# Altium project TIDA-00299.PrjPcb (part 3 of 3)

## Sheet AMIC110 ICE EVM_SC_0.SchDoc
size 431 x 279 mm; Date: Not shown in title block; ApprovedBy: Not shown in title block; CheckedBy: Not shown in title block; Author: Not shown in title block; CompanyName: Not shown in title block; Engineer: Not shown in title block; Organization: Not shown in title block; Address1: Not shown in title block; Address2: Not shown in title block; Address3: Not shown in title block; Address4: Not shown in title block; DocumentNumber: 1; Revision: Use project parameter SCH_Rev; SheetNumber: 5; SheetTotal: 1; PageSetup: Record=PageOptions¦CenterHorizontal=True¦CenterVertical=True¦PrintScale=1.00¦XCorrection=1.00¦YCorrection=1.00¦PrintKind=0¦BorderSize=5000000¦LeftOffset=0¦BottomOffset=0¦Orientation=2¦PaperLength=1000¦PaperWidth=1000¦Scale=100¦PaperSource=15¦PrintQuality=600¦MediaType=1¦DitherType=10¦PaperKind=Letter¦PrintScaleMode=1
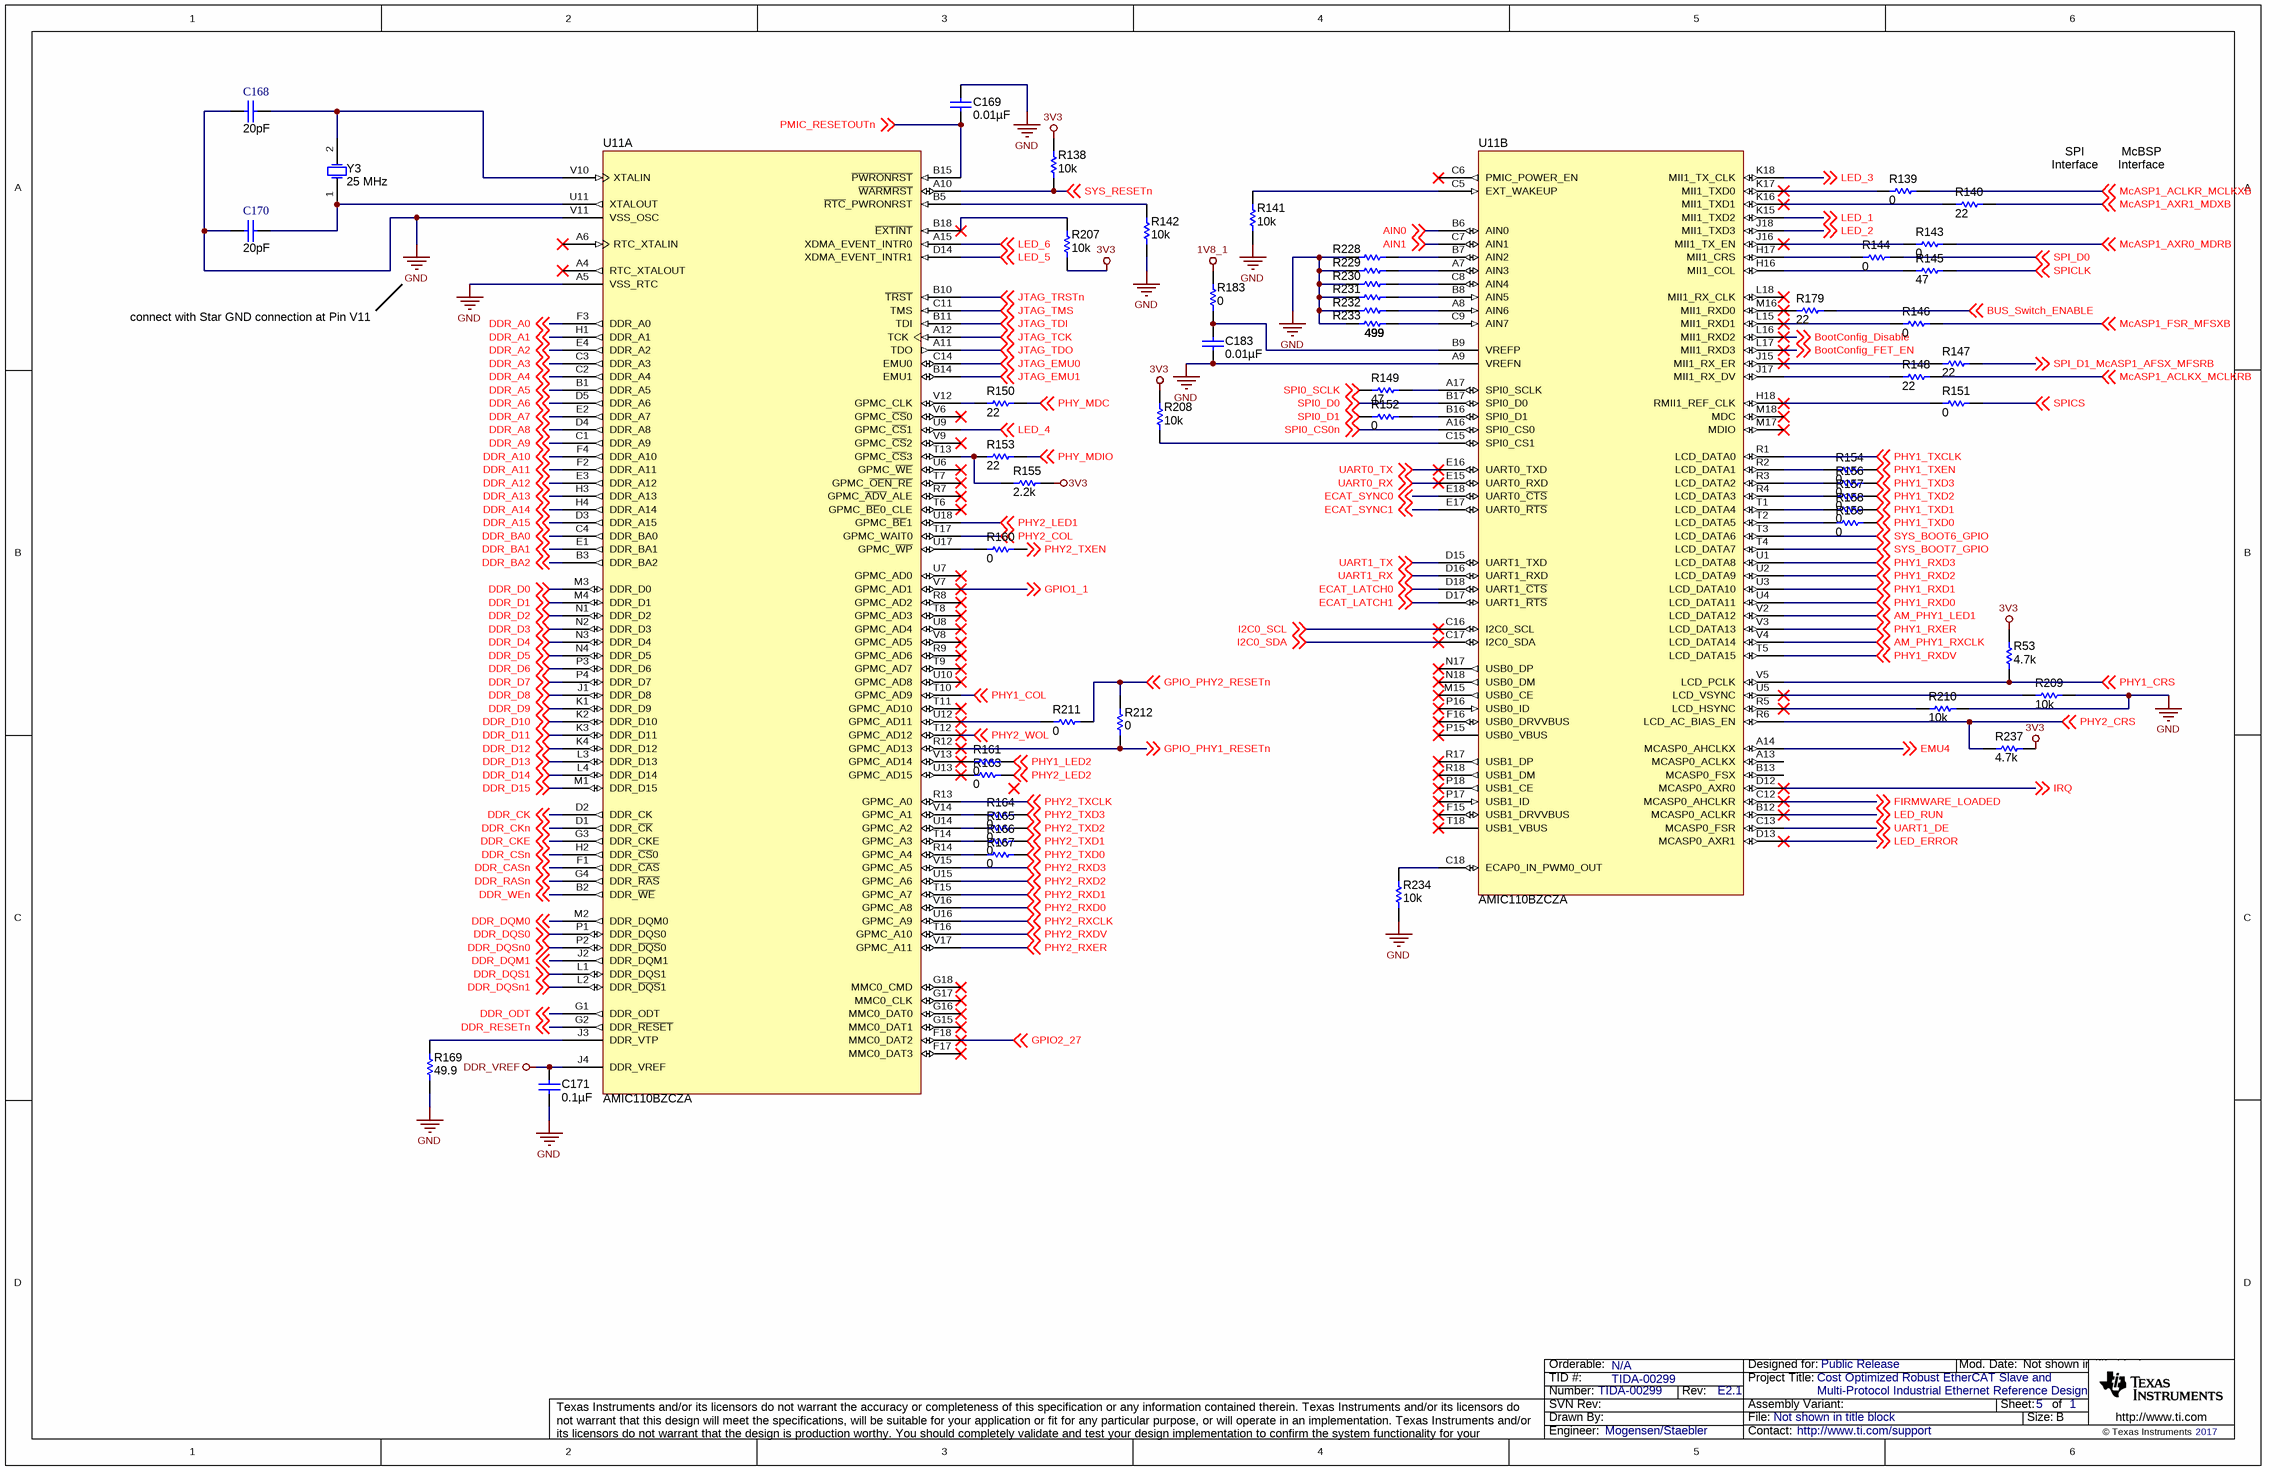
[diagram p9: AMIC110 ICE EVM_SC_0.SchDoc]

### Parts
C168  ValueDisplayed: 20pF  [0402]  (hidden comment: GRM1555C1H200JA01D)
C169  ValueDisplayed: 0.01µF  [0201L]  (hidden comment: GRM033R71A103KA01D)
C170  ValueDisplayed: 20pF  [0402]  (hidden comment: GRM1555C1H200JA01D)
C171  ValueDisplayed: 0.1µF  [0402]  (hidden comment: GRM155R70J104KA01D)
C183  ValueDisplayed: 0.01µF  [0201L]  (hidden comment: GRM033R71A103KA01D)
R53  ValueDisplayed: 4.7k  [0402L]  (hidden comment: CRCW04024K70JNED)
R138  ValueDisplayed: 10k  [0402L]  (hidden comment: CRCW040210K0JNED)
R139  ValueDisplayed: 0  [0402L]  (hidden comment: CRCW04020000Z0ED)
R140  ValueDisplayed: 22  [0402L]  (hidden comment: CRCW040222R0JNED)
R141  ValueDisplayed: 10k  [0402L]  (hidden comment: CRCW040210K0JNED)
R142  ValueDisplayed: 10k  [0402L]  (hidden comment: CRCW040210K0JNED)
R143  ValueDisplayed: 0  [0402L]  (hidden comment: CRCW04020000Z0ED)
R144  ValueDisplayed: 0  [0402L]  (hidden comment: CRCW04020000Z0ED)
R145  ValueDisplayed: 47  [0402L]  (hidden comment: CRCW040247R0JNED)
R146  ValueDisplayed: 0  [0402L]  (hidden comment: CRCW04020000Z0ED)
R147  ValueDisplayed: 22  [0402L]  (hidden comment: CRCW040222R0JNED)
R148  ValueDisplayed: 22  [0402L]  (hidden comment: CRCW040222R0JNED)
R149  ValueDisplayed: 47  [0402L]  (hidden comment: CRCW040247R0JNED)
R150  ValueDisplayed: 22  [0402L]  (hidden comment: CRCW040222R0JNED)
R151  ValueDisplayed: 0  [0402L]  (hidden comment: CRCW04020000Z0ED)
R152  ValueDisplayed: 0  [0402L]  (hidden comment: CRCW04020000Z0ED)
R153  ValueDisplayed: 22  [0402L]  (hidden comment: CRCW040222R0JNED)
R154  ValueDisplayed: 0  [0402L]  (hidden comment: CRCW04020000Z0ED)
R155  ValueDisplayed: 2.2k  [0402L]  (hidden comment: CRCW04022K20JNED)
R156  ValueDisplayed: 0  [0402L]  (hidden comment: CRCW04020000Z0ED)
R157  ValueDisplayed: 0  [0402L]  (hidden comment: CRCW04020000Z0ED)
R158  ValueDisplayed: 0  [0402L]  (hidden comment: CRCW04020000Z0ED)
R159  ValueDisplayed: 0  [0402L]  (hidden comment: CRCW04020000Z0ED)
R160  ValueDisplayed: 0  [0402L]  (hidden comment: CRCW04020000Z0ED)
R161  ValueDisplayed: 0  [0402L]  (hidden comment: CRCW04020000Z0ED)
R163  ValueDisplayed: 0  [0402L]  (hidden comment: CRCW04020000Z0ED)
R164  ValueDisplayed: 0  [0402L]  (hidden comment: CRCW04020000Z0ED)
R165  ValueDisplayed: 0  [0402L]  (hidden comment: CRCW04020000Z0ED)
R166  ValueDisplayed: 0  [0402L]  (hidden comment: CRCW04020000Z0ED)
R167  ValueDisplayed: 0  [0402L]  (hidden comment: CRCW04020000Z0ED)
R169  ValueDisplayed: 49.9  [0402]  (hidden comment: CRCW040249R9FKED)
R179  ValueDisplayed: 22  [0402L]  (hidden comment: CRCW040222R0JNED)
R183  ValueDisplayed: 0  [0402L]  (hidden comment: CRCW04020000Z0ED)
R207  ValueDisplayed: 10k  [0402L]  (hidden comment: CRCW040210K0JNED)
R208  ValueDisplayed: 10k  [0402L]  (hidden comment: CRCW040210K0JNED)
R209  ValueDisplayed: 10k  [0402L]  (hidden comment: CRCW040210K0JNED)
R210  ValueDisplayed: 10k  [0402L]  (hidden comment: CRCW040210K0JNED)
R211  ValueDisplayed: 0  [0402L]  (hidden comment: CRCW04020000Z0ED)
R212  ValueDisplayed: 0  [0402L]  (hidden comment: CRCW04020000Z0ED)
R228  ValueDisplayed: 499  [0201L]  (hidden comment: CRCW0201499RFKED)
R229  ValueDisplayed: 499  [0201L]  (hidden comment: CRCW0201499RFKED)
R230  ValueDisplayed: 499  [0201L]  (hidden comment: CRCW0201499RFKED)
R231  ValueDisplayed: 499  [0201L]  (hidden comment: CRCW0201499RFKED)
R232  ValueDisplayed: 499  [0201L]  (hidden comment: CRCW0201499RFKED)
R233  ValueDisplayed: 499  [0201L]  (hidden comment: CRCW0201499RFKED)
R234  ValueDisplayed: 10k  [0402L]  (hidden comment: CRCW040210K0JNED)
R237  ValueDisplayed: 4.7k  [0402L]  (hidden comment: CRCW04024K70JNED)
U11  AMIC110BZCZA  [ZCZ0324A]  (parts A,B of 4)
Y3  Frequency: 25 MHz  [XTAL_ABM3]  (hidden comment: CTX1175TR-ND)

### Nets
1V8_1: R183.2
3V3: R53.2 R138.2 R155.2 R207.1 R208.1 R237.1
DDR_VREF: C171.1 U11.J4(DDR_VREF)
GND: C168.2 C169.1 C170.2 C171.2 C183.2 R141.1 R142.1 R169.1 R209.2 R210.2 R228.1 R229.1 R230.1 R231.1 R232.1 R233.1 R234.1 U11.A5(VSS_RTC) U11.A9(VREFN) U11.V11(VSS_OSC)
AIN0: U11.B6(AIN0) ; off-sheet AIN0
AIN1: U11.C7(AIN1) ; off-sheet AIN1
AM_PHY1_LED1: U11.V2(LCD_DATA12) ; off-sheet AM_PHY1_LED1
AM_PHY1_RXCLK: U11.V4(LCD_DATA14) ; off-sheet AM_PHY1_RXCLK
BootConfig_Disable: U11.L16(MII1_RXD2) ; off-sheet BootConfig_Disable
BootConfig_FET_EN: U11.L17(MII1_RXD3) ; off-sheet BootConfig_FET_EN
BUS_Switch_ENABLE: R179.2 ; off-sheet BUS_Switch_ENABLE
DDR_A0: U11.F3(DDR_A0) ; off-sheet DDR_A0
DDR_A1: U11.H1(DDR_A1) ; off-sheet DDR_A1
DDR_A2: U11.E4(DDR_A2) ; off-sheet DDR_A2
DDR_A3: U11.C3(DDR_A3) ; off-sheet DDR_A3
DDR_A4: U11.C2(DDR_A4) ; off-sheet DDR_A4
DDR_A5: U11.B1(DDR_A5) ; off-sheet DDR_A5
DDR_A6: U11.D5(DDR_A6) ; off-sheet DDR_A6
DDR_A7: U11.E2(DDR_A7) ; off-sheet DDR_A7
DDR_A8: U11.D4(DDR_A8) ; off-sheet DDR_A8
DDR_A9: U11.C1(DDR_A9) ; off-sheet DDR_A9
DDR_A10: U11.F4(DDR_A10) ; off-sheet DDR_A10
DDR_A11: U11.F2(DDR_A11) ; off-sheet DDR_A11
DDR_A12: U11.E3(DDR_A12) ; off-sheet DDR_A12
DDR_A13: U11.H3(DDR_A13) ; off-sheet DDR_A13
DDR_A14: U11.H4(DDR_A14) ; off-sheet DDR_A14
DDR_A15: U11.D3(DDR_A15) ; off-sheet DDR_A15
DDR_BA0: U11.C4(DDR_BA0) ; off-sheet DDR_BA0
DDR_BA1: U11.E1(DDR_BA1) ; off-sheet DDR_BA1
DDR_BA2: U11.B3(DDR_BA2) ; off-sheet DDR_BA2
DDR_CASn: U11.F1(DDR_~{CAS}) ; off-sheet DDR_CASn
DDR_CK: U11.D2(DDR_CK) ; off-sheet DDR_CK
DDR_CKE: U11.G3(DDR_CKE) ; off-sheet DDR_CKE
DDR_CKn: U11.D1(DDR_~{CK}) ; off-sheet DDR_CKn
DDR_CSn: U11.H2(DDR_~{CS}0) ; off-sheet DDR_CSn
DDR_D0: U11.M3(DDR_D0) ; off-sheet DDR_D0
DDR_D1: U11.M4(DDR_D1) ; off-sheet DDR_D1
DDR_D2: U11.N1(DDR_D2) ; off-sheet DDR_D2
DDR_D3: U11.N2(DDR_D3) ; off-sheet DDR_D3
DDR_D4: U11.N3(DDR_D4) ; off-sheet DDR_D4
DDR_D5: U11.N4(DDR_D5) ; off-sheet DDR_D5
DDR_D6: U11.P3(DDR_D6) ; off-sheet DDR_D6
DDR_D7: U11.P4(DDR_D7) ; off-sheet DDR_D7
DDR_D8: U11.J1(DDR_D8) ; off-sheet DDR_D8
DDR_D9: U11.K1(DDR_D9) ; off-sheet DDR_D9
DDR_D10: U11.K2(DDR_D10) ; off-sheet DDR_D10
DDR_D11: U11.K3(DDR_D11) ; off-sheet DDR_D11
DDR_D12: U11.K4(DDR_D12) ; off-sheet DDR_D12
DDR_D13: U11.L3(DDR_D13) ; off-sheet DDR_D13
DDR_D14: U11.L4(DDR_D14) ; off-sheet DDR_D14
DDR_D15: U11.M1(DDR_D15) ; off-sheet DDR_D15
DDR_DQM0: U11.M2(DDR_DQM0) ; off-sheet DDR_DQM0
DDR_DQM1: U11.J2(DDR_DQM1) ; off-sheet DDR_DQM1
DDR_DQS0: U11.P1(DDR_DQS0) ; off-sheet DDR_DQS0
DDR_DQS1: U11.L1(DDR_DQS1) ; off-sheet DDR_DQS1
DDR_DQSn0: U11.P2(DDR_~{DQS}0) ; off-sheet DDR_DQSn0
DDR_DQSn1: U11.L2(DDR_~{DQS}1) ; off-sheet DDR_DQSn1
DDR_ODT: U11.G1(DDR_ODT) ; off-sheet DDR_ODT
DDR_RASn: U11.G4(DDR_~{RAS}) ; off-sheet DDR_RASn
DDR_RESETn: U11.G2(DDR_~{RESET}) ; off-sheet DDR_RESETn
DDR_WEn: U11.B2(DDR_~{WE}) ; off-sheet DDR_WEn
ECAT_LATCH0: U11.D18(UART1_~{CTS}) ; off-sheet ECAT_LATCH0
ECAT_LATCH1: U11.D17(UART1_~{RTS}) ; off-sheet ECAT_LATCH1
ECAT_SYNC0: U11.E18(UART0_~{CTS}) ; off-sheet ECAT_SYNC0
ECAT_SYNC1: U11.E17(UART0_~{RTS}) ; off-sheet ECAT_SYNC1
EMU4: U11.A14(MCASP0_AHCLKX) ; off-sheet EMU4
FIRMWARE_LOADED: U11.C12(MCASP0_AHCLKR) ; off-sheet FIRMWARE_LOADED
GPIO1_1: U11.V7(GPMC_AD1) ; off-sheet GPIO1_1
GPIO2_27: U11.F18(MMC0_DAT2) ; off-sheet GPIO2_27
GPIO_PHY1_RESETn: R212.2 U11.R12(GPMC_AD13) ; off-sheet GPIO_PHY1_RESETn
GPIO_PHY2_RESETn: R211.1 R212.1 ; off-sheet GPIO_PHY2_RESETn
I2C0_SCL: U11.C16(I2C0_SCL) ; off-sheet I2C0_SCL
I2C0_SDA: U11.C17(I2C0_SDA) ; off-sheet I2C0_SDA
IRQ: U11.D12(MCASP0_AXR0) ; off-sheet IRQ
JTAG_EMU0: U11.C14(EMU0) ; off-sheet JTAG_EMU0
JTAG_EMU1: U11.B14(EMU1) ; off-sheet JTAG_EMU1
JTAG_TCK: U11.A12(TCK) ; off-sheet JTAG_TCK
JTAG_TDI: U11.B11(TDI) ; off-sheet JTAG_TDI
JTAG_TDO: U11.A11(TDO) ; off-sheet JTAG_TDO
JTAG_TMS: U11.C11(TMS) ; off-sheet JTAG_TMS
JTAG_TRSTn: U11.B10(~{TRST}) ; off-sheet JTAG_TRSTn
LED_1: U11.K15(MII1_TXD2) ; off-sheet LED_1
LED_2: U11.J18(MII1_TXD3) ; off-sheet LED_2
LED_3: U11.K18(MII1_TX_CLK) ; off-sheet LED_3
LED_4: U11.U9(GPMC_~{CS}1) ; off-sheet LED_4
LED_5: U11.D14(XDMA_EVENT_INTR1) ; off-sheet LED_5
LED_6: U11.A15(XDMA_EVENT_INTR0) ; off-sheet LED_6
LED_ERROR: U11.D13(MCASP0_AXR1) ; off-sheet LED_ERROR
LED_RUN: U11.B12(MCASP0_ACLKR) ; off-sheet LED_RUN
McASP1_ACLKR_MCLKXB: R139.2 ; off-sheet McASP1_ACLKR_MCLKXB
McASP1_ACLKX_MCLKRB: R148.2 ; off-sheet McASP1_ACLKX_MCLKRB
McASP1_AXR0_MDRB: R143.2 ; off-sheet McASP1_AXR0_MDRB
McASP1_AXR1_MDXB: R140.2 ; off-sheet McASP1_AXR1_MDXB
McASP1_FSR_MFSXB: R146.2 ; off-sheet McASP1_FSR_MFSXB
PHY1_COL: U11.T10(GPMC_AD9) ; off-sheet PHY1_COL
PHY1_CRS: R53.1 U11.V5(LCD_PCLK) ; off-sheet PHY1_CRS
PHY1_LED2: R161.1 ; off-sheet PHY1_LED2
PHY1_RXD0: U11.U4(LCD_DATA11) ; off-sheet PHY1_RXD0
PHY1_RXD1: U11.U3(LCD_DATA10) ; off-sheet PHY1_RXD1
PHY1_RXD2: U11.U2(LCD_DATA9) ; off-sheet PHY1_RXD2
PHY1_RXD3: U11.U1(LCD_DATA8) ; off-sheet PHY1_RXD3
PHY1_RXDV: U11.T5(LCD_DATA15) ; off-sheet PHY1_RXDV
PHY1_RXER: U11.V3(LCD_DATA13) ; off-sheet PHY1_RXER
PHY1_TXCLK: U11.R1(LCD_DATA0) ; off-sheet PHY1_TXCLK
PHY1_TXD0: R159.2 ; off-sheet PHY1_TXD0
PHY1_TXD1: R158.2 ; off-sheet PHY1_TXD1
PHY1_TXD2: R157.2 ; off-sheet PHY1_TXD2
PHY1_TXD3: R156.2 ; off-sheet PHY1_TXD3
PHY1_TXEN: R154.2 ; off-sheet PHY1_TXEN
PHY2_COL: U11.T17(GPMC_WAIT0) ; off-sheet PHY2_COL
PHY2_CRS: R237.2 U11.R6(LCD_AC_BIAS_EN) ; off-sheet PHY2_CRS
PHY2_LED1: U11.U18(GPMC_~{BE}1) ; off-sheet PHY2_LED1
PHY2_LED2: R163.1 ; off-sheet PHY2_LED2
PHY2_RXCLK: U11.U16(GPMC_A9) ; off-sheet PHY2_RXCLK
PHY2_RXD0: U11.V16(GPMC_A8) ; off-sheet PHY2_RXD0
PHY2_RXD1: U11.T15(GPMC_A7) ; off-sheet PHY2_RXD1
PHY2_RXD2: U11.U15(GPMC_A6) ; off-sheet PHY2_RXD2
PHY2_RXD3: U11.V15(GPMC_A5) ; off-sheet PHY2_RXD3
PHY2_RXDV: U11.T16(GPMC_A10) ; off-sheet PHY2_RXDV
PHY2_RXER: U11.V17(GPMC_A11) ; off-sheet PHY2_RXER
PHY2_TXCLK: U11.R13(GPMC_A0) ; off-sheet PHY2_TXCLK
PHY2_TXD0: R167.2 ; off-sheet PHY2_TXD0
PHY2_TXD1: R166.2 ; off-sheet PHY2_TXD1
PHY2_TXD2: R165.2 ; off-sheet PHY2_TXD2
PHY2_TXD3: R164.2 ; off-sheet PHY2_TXD3
PHY2_TXEN: R160.2 ; off-sheet PHY2_TXEN
PHY2_WOL: U11.T12(GPMC_AD12) ; off-sheet PHY2_WOL
PHY_MDC: R150.1 ; off-sheet PHY_MDC
PHY_MDIO: R153.1 ; off-sheet PHY_MDIO
PMIC_RESETOUTn: C169.2 U11.B15(~{PWRONRST}) ; off-sheet PMIC_RESETOUTn
SPI0_CS0n: U11.A16(SPI0_CS0) ; off-sheet SPI0_CS0n
SPI0_D0: U11.B17(SPI0_D0) ; off-sheet SPI0_D0
SPI0_D1: R152.1 ; off-sheet SPI0_D1
SPI0_SCLK: R149.1 ; off-sheet SPI0_SCLK
SPI_D0: R144.2 ; off-sheet SPI_D0
SPI_D1_McASP1_AFSX_MFSRB: R147.2 ; off-sheet SPI_D1_McASP1_AFSX_MFSRB
SPICLK: R145.2 ; off-sheet SPICLK
SPICS: R151.2 ; off-sheet SPICS
SYS_BOOT6_GPIO: U11.T3(LCD_DATA6) ; off-sheet SYS_BOOT6_GPIO
SYS_BOOT7_GPIO: U11.T4(LCD_DATA7) ; off-sheet SYS_BOOT7_GPIO
SYS_RESETn: R138.1 U11.A10(~{WARMRST}) ; off-sheet SYS_RESETn
UART0_RX: U11.E15(UART0_RXD) ; off-sheet UART0_RX
UART0_TX: U11.E16(UART0_TXD) ; off-sheet UART0_TX
UART1_DE: U11.C13(MCASP0_FSR) ; off-sheet UART1_DE
UART1_RX: U11.D16(UART1_RXD) ; off-sheet UART1_RX
UART1_TX: U11.D15(UART1_TXD) ; off-sheet UART1_TX
NetC168_1: C168.1 U11.V10(XTALIN) Y3.2(OSC2)
NetC170_1: C170.1 U11.U11(XTALOUT) Y3.1(OSC1)
NetC183_1: C183.1 R183.1 U11.B9(VREFP)
NetR139_1: R139.1 U11.K17(MII1_TXD0)
NetR140_1: R140.1 U11.K16(MII1_TXD1)
NetR141_2: R141.2 U11.C5(EXT_WAKEUP)
NetR142_2: R142.2 U11.B5(~{RTC}_PWRONRST)
NetR143_1: R143.1 U11.J16(MII1_TX_EN)
NetR144_1: R144.1 U11.H17(MII1_CRS)
NetR145_1: R145.1 U11.H16(MII1_COL)
NetR146_1: R146.1 U11.L15(MII1_RXD1)
NetR147_1: R147.1 U11.J15(MII1_RX_ER)
NetR148_1: R148.1 U11.J17(MII1_RX_DV)
NetR149_2: R149.2 U11.A17(SPI0_SCLK)
NetR150_2: R150.2 U11.V12(GPMC_CLK)
NetR151_1: R151.1 U11.H18(RMII1_REF_CLK)
NetR152_2: R152.2 U11.B16(SPI0_D1)
NetR153_2: R153.2 R155.1 U11.T13(GPMC_~{CS}3)
NetR154_1: R154.1 U11.R2(LCD_DATA1)
NetR156_1: R156.1 U11.R3(LCD_DATA2)
NetR157_1: R157.1 U11.R4(LCD_DATA3)
NetR158_1: R158.1 U11.T1(LCD_DATA4)
NetR159_1: R159.1 U11.T2(LCD_DATA5)
NetR160_1: R160.1 U11.U17(GPMC_~{WP})
NetR161_2: R161.2 U11.V13(GPMC_AD14)
NetR163_2: R163.2 U11.U13(GPMC_AD15)
NetR164_1: R164.1 U11.V14(GPMC_A1)
NetR165_1: R165.1 U11.U14(GPMC_A2)
NetR166_1: R166.1 U11.T14(GPMC_A3)
NetR167_1: R167.1 U11.R14(GPMC_A4)
NetR169_2: R169.2 U11.J3(DDR_VTP)
NetR179_1: R179.1 U11.M16(MII1_RXD0)
NetR207_2: R207.2 U11.B18(~{EXTINT})
NetR208_2: R208.2 U11.C15(SPI0_CS1)
NetR209_1: R209.1 U11.U5(LCD_VSYNC)
NetR210_1: R210.1 U11.R5(LCD_HSYNC)
NetR211_2: R211.2 U11.U12(GPMC_AD11)
NetR228_2: R228.2 U11.B7(AIN2)
NetR229_2: R229.2 U11.A7(AIN3)
NetR230_2: R230.2 U11.C8(AIN4)
NetR231_2: R231.2 U11.B8(AIN5)
NetR232_2: R232.2 U11.A8(AIN6)
NetR233_2: R233.2 U11.C9(AIN7)
NetR234_2: R234.2 U11.C18(ECAP0_IN_PWM0_OUT)

Not connected (* = marked no-connect by the designer): U11 A4(RTC_XTALOUT)* A6(RTC_XTALIN)* A13(MCASP0_ACLKX) B13(MCASP0_FSX) C6(PMIC_POWER_EN)* F15(USB1_DRVVBUS)* F16(USB0_DRVVBUS)* F17(MMC0_DAT3)* G15(MMC0_DAT1)* G16(MMC0_DAT0)* G17(MMC0_CLK)* G18(MMC0_CMD)* L18(MII1_RX_CLK)* M15(USB0_CE)* M17(MDIO)* M18(MDC)* N17(USB0_DP)* N18(USB0_DM)* P15(USB0_VBUS)* P16(USB0_ID)* P17(USB1_ID)* P18(USB1_CE)* R7(GPMC_~{ADV}_ALE)* R8(GPMC_AD2)* R9(GPMC_AD6)* R17(USB1_DP)* R18(USB1_DM)* T6(GPMC_~{BE}0_CLE)* T7(GPMC_~{OEN_RE})* T8(GPMC_AD3)* T9(GPMC_AD7)* T11(GPMC_AD10)* T18(USB1_VBUS)* U6(GPMC_~{WE})* U7(GPMC_AD0)* U8(GPMC_AD4)* U10(GPMC_AD8)* V6(GPMC_~{CS}0)* V8(GPMC_AD5)* V9(GPMC_~{CS}2)*

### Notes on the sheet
- SPI
- Interface
- McBSP
- connect with Star GND connection at Pin V11

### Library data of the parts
C168 C170 = GRM1555C1H200JA01D: CAP, CERM, 20 pF, 50 V, +/- 5%, C0G/NP0, 0402; Manufacturer: MuRata; Polarized: N; CompType: Capacitor; Value: 20pF; U/M: EA; Cap_F: 0.000000000020; Tolerance_%: 5; Value1: Unknown; VDC_V: 50; Value2: 50V; TaMin_C: -55; TaMax_C: 125; AEC Category: Q200
C169 C183 = GRM033R71A103KA01D: CAP, CERM, 0.01 µF, 10 V, +/- 10%, X7R, 0201; Manufacturer: MuRata; Polarized: N; CompType: Capacitor; Value: 0.01uF; U/M: EA; Cap_F: 0.00000001; Tolerance_%: 10; Value1: Unknown; Value2: 10V; TaMin_C: -55; TaMax_C: 125; Cap_Case: 0201
C171 = GRM155R70J104KA01D: CAP, CERM, 0.1 µF, 6.3 V, +/- 10%, X7R, 0402; Manufacturer: MuRata; Polarized: N; CompType: Capacitor; Value: 0.1uF; U/M: EA; Cap_F: 0.0000001; Tolerance_%: 10; Value1: Unknown; VDC_V: 6.3; Value2: 6.3V; TaMin_C: -55; TaMax_C: 125; AEC Category: Q200
R53 R237 = CRCW04024K70JNED: RES, 4.7 k, 5%, 0.063 W, 0402; Manufacturer: Vishay-Dale; CompType: Resistor; Value: 4.7k; Res_ohm: 4700; Value_Code: 4k70; Tolerance_%: 5; Power_W: 0.063; Value2: 0.063W; VDC_V: 50; TempCo: 200 ppm/C; EIA_Code: E24; U/M: EA
R138 R141 R142 R207-R210 R234 = CRCW040210K0JNED: RES, 10 k, 5%, 0.063 W, 0402; Manufacturer: Vishay-Dale; CompType: Resistor; Value: 10k; Res_ohm: 10000; Value_Code: 10k0; Tolerance_%: 5; Power_W: 0.063; Value2: 0.063W; VDC_V: 50; TempCo: 200 ppm/C; EIA_Code: E24; U/M: EA
R139 R143 R144 R146 R151 R152 R154 R156-R161 R163-R167 R183 R211 R212 = CRCW04020000Z0ED: RES, 0, 5%, 0.063 W, 0402; Manufacturer: Vishay-Dale; CompType: Resistor; Value: 0; Value_Code: 0000; Tolerance_%: 5; Power_W: 0.063; Value2: 0.063W; VDC_V: 50; TempCo: 200 ppm/C; EIA_Code: E24; U/M: EA; AEC Category: Q200
R140 R147 R148 R150 R153 R179 = CRCW040222R0JNED: RES, 22, 5%, 0.063 W, 0402; Manufacturer: Vishay-Dale; CompType: Resistor; Value: 22; Value_Code: 22R0; Tolerance_%: 5; Power_W: 0.063; Value2: 0.063W; VDC_V: 50; TempCo: 200 ppm/C; EIA_Code: E24; U/M: EA; AEC Category: Q200
R145 R149 = CRCW040247R0JNED: RES, 47, 5%, 0.063 W, 0402; Manufacturer: Vishay-Dale; CompType: Resistor; Value: 47; Value_Code: 47R0; Tolerance_%: 5; Power_W: 0.063; Value2: 0.063W; VDC_V: 50; TempCo: 200 ppm/C; EIA_Code: E24; U/M: EA; AEC Category: Q200; SizeArea_mm2: 0.5; SizeX_mm: 1; SizeZ_mm: 0.6
R155 = CRCW04022K20JNED: RES, 2.2 k, 5%, 0.063 W, 0402; Manufacturer: Vishay-Dale; CompType: Resistor; Value: 2.2k; Res_ohm: 2200; Value_Code: 2k20; Tolerance_%: 5; Power_W: 0.063; Value2: 0.063W; VDC_V: 50; TempCo: 200 ppm/C; EIA_Code: E24; U/M: EA
R169 = CRCW040249R9FKED: RES, 49.9, 1%, 0.063 W, 0402; Manufacturer: Vishay-Dale; CompType: Resistor; Value: 49.9; Value_Code: 49R9; Tolerance_%: 1; Power_W: 0.063; Value2: 0.063W; VDC_V: 50; TempCo: 100 ppm/C; EIA_Code: E96; U/M: EA; AEC Category: Q200
R228-R233 = CRCW0201499RFKED: RES, 499, 1%, 0.05 W, 0201; Manufacturer: Vishay-Dale; CompType: Resistor; Value: 499; Value_Code: 499R; Tolerance_%: 1; Power_W: 0.05; Value2: 0.05W; VDC_V: 30; TempCo: 100 ppm/C; SizeArea_mm2: 0.18; SizeAreaWB_mm2: 2.08; SizeX_mm: 0.6; SizeY_mm: 0.3; SizeZ_mm: 0.26; EIA_Code: E96; U/M: EA; AEC Category: Q200
U11 = AMIC110BZCZA: Sitara Processors, ZCZ0324A; Alternate Manufacturer: None; Manufacturer: Texas Instruments; SymbolCreator: Altium; CompType: IC; U/M: EA
Y3 = CTX1175TR-ND: Crystal, 25 MHz, 18 pF, SMD; Manufacturer: CTS ELECTRONIC COMPONENTS; U/M: EA; TaMin_C: -40; TaMax_C: 85; Frequency Stability: ±20ppm

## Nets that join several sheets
1V1: AMIC110 ICE EVM_Power (R77.2), AMIC110 ICE EVM_PS (50 pins)
1V5: AMIC110 ICE EVM_Memory (36 pins), AMIC110 ICE EVM_Power (R81.2), AMIC110 ICE EVM_PS (16 pins)
1V8_1: AMIC110 ICE EVM_Power (R94.2), AMIC110 ICE EVM_PS (17 pins), AMIC110 ICE EVM_SC_0 (R183.2)
1V8_2: AMIC110 ICE EVM_Power (R98.2), AMIC110 ICE EVM_PS (18 pins)
3V3: AMIC110 ICE EVM_BootConfig (22 pins), AMIC110 ICE EVM_Interfaces (25 pins), AMIC110 ICE EVM_Memory (13 pins), AMIC110 ICE EVM_PHY (36 pins), AMIC110 ICE EVM_Power (R89.2 R101.2), AMIC110 ICE EVM_PS (48 pins), AMIC110 ICE EVM_SC_0 (6 pins)
DDR_VREF: AMIC110 ICE EVM_Memory (6 pins), AMIC110 ICE EVM_SC_0 (C171.1 U11.J4)
GND: AMIC110 ICE EVM_BootConfig (25 pins), AMIC110 ICE EVM_Interfaces (37 pins), AMIC110 ICE EVM_Led (24 pins), AMIC110 ICE EVM_Memory (50 pins), AMIC110 ICE EVM_PHY (60 pins), AMIC110 ICE EVM_Power (42 pins), AMIC110 ICE EVM_PS (119 pins), AMIC110 ICE EVM_SC_0 (20 pins)
Vin5V: AMIC110 ICE EVM_Led (6 pins), AMIC110 ICE EVM_Power (16 pins)
AIN0: AMIC110 ICE EVM_Interfaces (R180.2 R184.2), AMIC110 ICE EVM_SC_0 (U11.B6)
AIN1: AMIC110 ICE EVM_Interfaces (R181.2 R185.2), AMIC110 ICE EVM_SC_0 (U11.C7)
AM_PHY1_LED1: AMIC110 ICE EVM_BootConfig (R203.2 U10.D2), AMIC110 ICE EVM_SC_0 (U11.V2)
AM_PHY1_RXCLK: AMIC110 ICE EVM_BootConfig (R206.2 U10.A1), AMIC110 ICE EVM_SC_0 (U11.V4)
BootConfig_Disable: AMIC110 ICE EVM_BootConfig (6 pins), AMIC110 ICE EVM_SC_0 (U11.L16)
BootConfig_FET_EN: AMIC110 ICE EVM_BootConfig (R121.2 U10.B2 U10.C1), AMIC110 ICE EVM_SC_0 (U11.L17)
BUS_Switch_ENABLE: AMIC110 ICE EVM_Interfaces (6 pins), AMIC110 ICE EVM_SC_0 (R179.2)
DDR_A0: AMIC110 ICE EVM_Memory (U1.N3), AMIC110 ICE EVM_SC_0 (U11.F3)
DDR_A1: AMIC110 ICE EVM_Memory (U1.P7), AMIC110 ICE EVM_SC_0 (U11.H1)
DDR_A2: AMIC110 ICE EVM_Memory (U1.P3), AMIC110 ICE EVM_SC_0 (U11.E4)
DDR_A3: AMIC110 ICE EVM_Memory (U1.N2), AMIC110 ICE EVM_SC_0 (U11.C3)
DDR_A4: AMIC110 ICE EVM_Memory (U1.P8), AMIC110 ICE EVM_SC_0 (U11.C2)
DDR_A5: AMIC110 ICE EVM_Memory (U1.P2), AMIC110 ICE EVM_SC_0 (U11.B1)
DDR_A6: AMIC110 ICE EVM_Memory (U1.R8), AMIC110 ICE EVM_SC_0 (U11.D5)
DDR_A7: AMIC110 ICE EVM_Memory (U1.R2), AMIC110 ICE EVM_SC_0 (U11.E2)
DDR_A8: AMIC110 ICE EVM_Memory (U1.T8), AMIC110 ICE EVM_SC_0 (U11.D4)
DDR_A9: AMIC110 ICE EVM_Memory (U1.R3), AMIC110 ICE EVM_SC_0 (U11.C1)
DDR_A10: AMIC110 ICE EVM_Memory (U1.L7), AMIC110 ICE EVM_SC_0 (U11.F4)
DDR_A11: AMIC110 ICE EVM_Memory (U1.R7), AMIC110 ICE EVM_SC_0 (U11.F2)
DDR_A12: AMIC110 ICE EVM_Memory (U1.N7), AMIC110 ICE EVM_SC_0 (U11.E3)
DDR_A13: AMIC110 ICE EVM_Memory (U1.T3), AMIC110 ICE EVM_SC_0 (U11.H3)
DDR_A14: AMIC110 ICE EVM_Memory (U1.T7), AMIC110 ICE EVM_SC_0 (U11.H4)
DDR_A15: AMIC110 ICE EVM_Memory (U1.M7), AMIC110 ICE EVM_SC_0 (U11.D3)
DDR_BA0: AMIC110 ICE EVM_Memory (U1.M2), AMIC110 ICE EVM_SC_0 (U11.C4)
DDR_BA1: AMIC110 ICE EVM_Memory (U1.N8), AMIC110 ICE EVM_SC_0 (U11.E1)
DDR_BA2: AMIC110 ICE EVM_Memory (U1.M3), AMIC110 ICE EVM_SC_0 (U11.B3)
DDR_CASn: AMIC110 ICE EVM_Memory (U1.K3), AMIC110 ICE EVM_SC_0 (U11.F1)
DDR_CK: AMIC110 ICE EVM_Memory (U1.J7), AMIC110 ICE EVM_SC_0 (U11.D2)
DDR_CKE: AMIC110 ICE EVM_Memory (R36.2 U1.K9), AMIC110 ICE EVM_SC_0 (U11.G3)
DDR_CKn: AMIC110 ICE EVM_Memory (U1.K7), AMIC110 ICE EVM_SC_0 (U11.D1)
DDR_CSn: AMIC110 ICE EVM_Memory (U1.L2), AMIC110 ICE EVM_SC_0 (U11.H2)
DDR_D0: AMIC110 ICE EVM_Memory (U1.E3), AMIC110 ICE EVM_SC_0 (U11.M3)
DDR_D1: AMIC110 ICE EVM_Memory (U1.F7), AMIC110 ICE EVM_SC_0 (U11.M4)
DDR_D2: AMIC110 ICE EVM_Memory (U1.F2), AMIC110 ICE EVM_SC_0 (U11.N1)
DDR_D3: AMIC110 ICE EVM_Memory (U1.F8), AMIC110 ICE EVM_SC_0 (U11.N2)
DDR_D4: AMIC110 ICE EVM_Memory (U1.H3), AMIC110 ICE EVM_SC_0 (U11.N3)
DDR_D5: AMIC110 ICE EVM_Memory (U1.H8), AMIC110 ICE EVM_SC_0 (U11.N4)
DDR_D6: AMIC110 ICE EVM_Memory (U1.G2), AMIC110 ICE EVM_SC_0 (U11.P3)
DDR_D7: AMIC110 ICE EVM_Memory (U1.H7), AMIC110 ICE EVM_SC_0 (U11.P4)
DDR_D8: AMIC110 ICE EVM_Memory (U1.D7), AMIC110 ICE EVM_SC_0 (U11.J1)
DDR_D9: AMIC110 ICE EVM_Memory (U1.C3), AMIC110 ICE EVM_SC_0 (U11.K1)
DDR_D10: AMIC110 ICE EVM_Memory (U1.C8), AMIC110 ICE EVM_SC_0 (U11.K2)
DDR_D11: AMIC110 ICE EVM_Memory (U1.C2), AMIC110 ICE EVM_SC_0 (U11.K3)
DDR_D12: AMIC110 ICE EVM_Memory (U1.A7), AMIC110 ICE EVM_SC_0 (U11.K4)
DDR_D13: AMIC110 ICE EVM_Memory (U1.A2), AMIC110 ICE EVM_SC_0 (U11.L3)
DDR_D14: AMIC110 ICE EVM_Memory (U1.B8), AMIC110 ICE EVM_SC_0 (U11.L4)
DDR_D15: AMIC110 ICE EVM_Memory (U1.A3), AMIC110 ICE EVM_SC_0 (U11.M1)
DDR_DQM0: AMIC110 ICE EVM_Memory (U1.E7), AMIC110 ICE EVM_SC_0 (U11.M2)
DDR_DQM1: AMIC110 ICE EVM_Memory (U1.D3), AMIC110 ICE EVM_SC_0 (U11.J2)
DDR_DQS0: AMIC110 ICE EVM_Memory (U1.F3), AMIC110 ICE EVM_SC_0 (U11.P1)
DDR_DQS1: AMIC110 ICE EVM_Memory (U1.C7), AMIC110 ICE EVM_SC_0 (U11.L1)
DDR_DQSn0: AMIC110 ICE EVM_Memory (U1.G3), AMIC110 ICE EVM_SC_0 (U11.P2)
DDR_DQSn1: AMIC110 ICE EVM_Memory (U1.B7), AMIC110 ICE EVM_SC_0 (U11.L2)
DDR_ODT: AMIC110 ICE EVM_Memory (U1.K1), AMIC110 ICE EVM_SC_0 (U11.G1)
DDR_RASn: AMIC110 ICE EVM_Memory (U1.J3), AMIC110 ICE EVM_SC_0 (U11.G4)
DDR_RESETn: AMIC110 ICE EVM_Memory (R37.2 U1.T2), AMIC110 ICE EVM_SC_0 (U11.G2)
DDR_WEn: AMIC110 ICE EVM_Memory (U1.L3), AMIC110 ICE EVM_SC_0 (U11.B2)
ECAT_LATCH0: AMIC110 ICE EVM_Interfaces (R162.2 U13.6), AMIC110 ICE EVM_SC_0 (U11.D18)
ECAT_LATCH1: AMIC110 ICE EVM_Interfaces (R168.2 U13.7), AMIC110 ICE EVM_SC_0 (U11.D17)
ECAT_SYNC0: AMIC110 ICE EVM_Interfaces (R213.2 U15.2), AMIC110 ICE EVM_SC_0 (U11.E18)
ECAT_SYNC1: AMIC110 ICE EVM_Interfaces (R214.2 U15.3), AMIC110 ICE EVM_SC_0 (U11.E17)
EMU4: AMIC110 ICE EVM_Interfaces (R8.1), AMIC110 ICE EVM_SC_0 (U11.A14)
FIRMWARE_LOADED: AMIC110 ICE EVM_Interfaces (U13.8), AMIC110 ICE EVM_SC_0 (U11.C12)
GPIO1_1: AMIC110 ICE EVM_Interfaces (U14.2), AMIC110 ICE EVM_SC_0 (U11.V7)
GPIO2_27: AMIC110 ICE EVM_Interfaces (U15.5), AMIC110 ICE EVM_SC_0 (U11.F18)
GPIO_PHY1_RESETn: AMIC110 ICE EVM_PHY (R56.2 U3.18), AMIC110 ICE EVM_SC_0 (R212.2 U11.R12)
GPIO_PHY2_RESETn: AMIC110 ICE EVM_PHY (R69.2 U5.18), AMIC110 ICE EVM_SC_0 (R211.1 R212.1)
I2C0_SCL: AMIC110 ICE EVM_Memory (R218.1 U16.6), AMIC110 ICE EVM_SC_0 (U11.C16)
I2C0_SDA: AMIC110 ICE EVM_Memory (R219.1 U16.5), AMIC110 ICE EVM_SC_0 (U11.C17)
IRQ: AMIC110 ICE EVM_Interfaces (U14.9), AMIC110 ICE EVM_SC_0 (U11.D12)
JTAG_EMU0: AMIC110 ICE EVM_Interfaces (J1.13 R2.1), AMIC110 ICE EVM_SC_0 (U11.C14)
JTAG_EMU1: AMIC110 ICE EVM_Interfaces (J1.14 R11.1), AMIC110 ICE EVM_SC_0 (U11.B14)
JTAG_TCK: AMIC110 ICE EVM_Interfaces (R4.1 R5.1), AMIC110 ICE EVM_SC_0 (U11.A12)
JTAG_TDI: AMIC110 ICE EVM_Interfaces (J1.3), AMIC110 ICE EVM_SC_0 (U11.B11)
JTAG_TDO: AMIC110 ICE EVM_Interfaces (J1.7), AMIC110 ICE EVM_SC_0 (U11.A11)
JTAG_TMS: AMIC110 ICE EVM_Interfaces (J1.1), AMIC110 ICE EVM_SC_0 (U11.C11)
JTAG_TRSTn: AMIC110 ICE EVM_Interfaces (J1.2 R3.2), AMIC110 ICE EVM_SC_0 (U11.B10)
LED_1: AMIC110 ICE EVM_Led (Q1.1 R14.2), AMIC110 ICE EVM_SC_0 (U11.K15)
LED_2: AMIC110 ICE EVM_Led (Q2.1 R18.2), AMIC110 ICE EVM_SC_0 (U11.J18)
LED_3: AMIC110 ICE EVM_Led (Q3.1 R23.2), AMIC110 ICE EVM_SC_0 (U11.K18)
LED_4: AMIC110 ICE EVM_Led (Q4.1 R24.2), AMIC110 ICE EVM_SC_0 (U11.U9)
LED_5: AMIC110 ICE EVM_Interfaces (R7.1), AMIC110 ICE EVM_Led (Q5.1 R32.2), AMIC110 ICE EVM_SC_0 (U11.D14)
LED_6: AMIC110 ICE EVM_Interfaces (R6.1), AMIC110 ICE EVM_Led (Q6.1 R33.2), AMIC110 ICE EVM_SC_0 (U11.A15)
LED_ERROR: AMIC110 ICE EVM_Led (R28.1), AMIC110 ICE EVM_SC_0 (U11.D13)
LED_RUN: AMIC110 ICE EVM_Led (R19.2), AMIC110 ICE EVM_SC_0 (U11.B12)
McASP1_ACLKR_MCLKXB: AMIC110 ICE EVM_Interfaces (U13.4), AMIC110 ICE EVM_SC_0 (R139.2)
McASP1_ACLKX_MCLKRB: AMIC110 ICE EVM_Interfaces (R12.1), AMIC110 ICE EVM_SC_0 (R148.2)
McASP1_AXR0_MDRB: AMIC110 ICE EVM_Interfaces (U13.3), AMIC110 ICE EVM_SC_0 (R143.2)
McASP1_AXR1_MDXB: AMIC110 ICE EVM_Interfaces (U13.2), AMIC110 ICE EVM_SC_0 (R140.2)
McASP1_FSR_MFSXB: AMIC110 ICE EVM_Interfaces (U13.5), AMIC110 ICE EVM_SC_0 (R146.2)
PHY1_COL: AMIC110 ICE EVM_PHY (R52.1), AMIC110 ICE EVM_SC_0 (U11.T10)
PHY1_CRS: AMIC110 ICE EVM_PHY (U3.27), AMIC110 ICE EVM_SC_0 (R53.1 U11.V5)
PHY1_LED0: AMIC110 ICE EVM_Led (R20.2 R188.2), AMIC110 ICE EVM_PHY (U3.17)
PHY1_LED1: AMIC110 ICE EVM_BootConfig (U10.C2), AMIC110 ICE EVM_Led (R21.2 R235.2), AMIC110 ICE EVM_PHY (U3.24)
PHY1_LED2: AMIC110 ICE EVM_Led (R22.2), AMIC110 ICE EVM_PHY (R51.1), AMIC110 ICE EVM_SC_0 (R161.1)
PHY1_RXCLK: AMIC110 ICE EVM_BootConfig (U10.B1), AMIC110 ICE EVM_PHY (U3.25)
PHY1_RXD0: AMIC110 ICE EVM_BootConfig (R202.2), AMIC110 ICE EVM_PHY (U3.30), AMIC110 ICE EVM_SC_0 (U11.U4)
PHY1_RXD1: AMIC110 ICE EVM_BootConfig (R201.2), AMIC110 ICE EVM_PHY (U3.31), AMIC110 ICE EVM_SC_0 (U11.U3)
PHY1_RXD2: AMIC110 ICE EVM_BootConfig (R200.2), AMIC110 ICE EVM_PHY (U3.32), AMIC110 ICE EVM_SC_0 (U11.U2)
PHY1_RXD3: AMIC110 ICE EVM_BootConfig (R199.2), AMIC110 ICE EVM_PHY (U3.1), AMIC110 ICE EVM_SC_0 (U11.U1)
PHY1_RXDV: AMIC110 ICE EVM_BootConfig (R205.2), AMIC110 ICE EVM_PHY (U3.26), AMIC110 ICE EVM_SC_0 (U11.T5)
PHY1_RXER: AMIC110 ICE EVM_BootConfig (R204.2), AMIC110 ICE EVM_PHY (U3.28), AMIC110 ICE EVM_SC_0 (U11.V3)
PHY1_TXCLK: AMIC110 ICE EVM_BootConfig (R196.2), AMIC110 ICE EVM_PHY (U3.2), AMIC110 ICE EVM_SC_0 (U11.R1)
PHY1_TXD0: AMIC110 ICE EVM_BootConfig (R194.2), AMIC110 ICE EVM_PHY (U3.4), AMIC110 ICE EVM_SC_0 (R159.2)
PHY1_TXD1: AMIC110 ICE EVM_BootConfig (R193.2), AMIC110 ICE EVM_PHY (U3.5), AMIC110 ICE EVM_SC_0 (R158.2)
PHY1_TXD2: AMIC110 ICE EVM_BootConfig (R192.2), AMIC110 ICE EVM_PHY (U3.6), AMIC110 ICE EVM_SC_0 (R157.2)
PHY1_TXD3: AMIC110 ICE EVM_BootConfig (R191.2), AMIC110 ICE EVM_PHY (U3.7), AMIC110 ICE EVM_SC_0 (R156.2)
PHY1_TXEN: AMIC110 ICE EVM_BootConfig (R195.2), AMIC110 ICE EVM_PHY (U3.3), AMIC110 ICE EVM_SC_0 (R154.2)
PHY2_COL: AMIC110 ICE EVM_PHY (R73.1), AMIC110 ICE EVM_SC_0 (U11.T17)
PHY2_CRS: AMIC110 ICE EVM_PHY (U5.27), AMIC110 ICE EVM_SC_0 (R237.2 U11.R6)
PHY2_LED0: AMIC110 ICE EVM_Led (R29.2 R189.2), AMIC110 ICE EVM_PHY (U5.17)
PHY2_LED1: AMIC110 ICE EVM_Led (R30.2 R236.2), AMIC110 ICE EVM_PHY (U5.24), AMIC110 ICE EVM_SC_0 (U11.U18)
PHY2_LED2: AMIC110 ICE EVM_Led (R31.2), AMIC110 ICE EVM_PHY (R71.1), AMIC110 ICE EVM_SC_0 (R163.1)
PHY2_RXCLK: AMIC110 ICE EVM_PHY (U5.25), AMIC110 ICE EVM_SC_0 (U11.U16)
PHY2_RXD0: AMIC110 ICE EVM_PHY (U5.30), AMIC110 ICE EVM_SC_0 (U11.V16)
PHY2_RXD1: AMIC110 ICE EVM_PHY (R67.1 R72.2 U5.31), AMIC110 ICE EVM_SC_0 (U11.T15)
PHY2_RXD2: AMIC110 ICE EVM_PHY (R68.1 R75.2 U5.32), AMIC110 ICE EVM_SC_0 (U11.U15)
PHY2_RXD3: AMIC110 ICE EVM_PHY (U5.1), AMIC110 ICE EVM_SC_0 (U11.V15)
PHY2_RXDV: AMIC110 ICE EVM_PHY (U5.26), AMIC110 ICE EVM_SC_0 (U11.T16)
PHY2_RXER: AMIC110 ICE EVM_PHY (U5.28), AMIC110 ICE EVM_SC_0 (U11.V17)
PHY2_TXCLK: AMIC110 ICE EVM_PHY (U5.2), AMIC110 ICE EVM_SC_0 (U11.R13)
PHY2_TXD0: AMIC110 ICE EVM_PHY (U5.4), AMIC110 ICE EVM_SC_0 (R167.2)
PHY2_TXD1: AMIC110 ICE EVM_PHY (U5.5), AMIC110 ICE EVM_SC_0 (R166.2)
PHY2_TXD2: AMIC110 ICE EVM_PHY (U5.6), AMIC110 ICE EVM_SC_0 (R165.2)
PHY2_TXD3: AMIC110 ICE EVM_PHY (U5.7), AMIC110 ICE EVM_SC_0 (R164.2)
PHY2_TXEN: AMIC110 ICE EVM_PHY (U5.3), AMIC110 ICE EVM_SC_0 (R160.2)
PHY2_WOL: AMIC110 ICE EVM_PHY (R65.2), AMIC110 ICE EVM_SC_0 (U11.T12)
PHY_MDC: AMIC110 ICE EVM_PHY (U3.20 U5.20), AMIC110 ICE EVM_SC_0 (R150.1)
PHY_MDIO: AMIC110 ICE EVM_PHY (U3.19 U5.19), AMIC110 ICE EVM_SC_0 (R153.1)
PMIC_RESETOUTn: AMIC110 ICE EVM_Power (R102.2), AMIC110 ICE EVM_SC_0 (C169.2 U11.B15)
SPI0_CS0n: AMIC110 ICE EVM_Memory (R217.1 U2.1), AMIC110 ICE EVM_SC_0 (U11.A16)
SPI0_D0: AMIC110 ICE EVM_Memory (R239.1 U2.2), AMIC110 ICE EVM_SC_0 (U11.B17)
SPI0_D1: AMIC110 ICE EVM_Memory (R238.1 U2.5), AMIC110 ICE EVM_SC_0 (R152.1)
SPI0_SCLK: AMIC110 ICE EVM_Memory (R240.1 U2.6), AMIC110 ICE EVM_SC_0 (R149.1)
SPI_D0: AMIC110 ICE EVM_Interfaces (U14.5), AMIC110 ICE EVM_SC_0 (R144.2)
SPI_D1_McASP1_AFSX_MFSRB: AMIC110 ICE EVM_Interfaces (R13.1 U14.6), AMIC110 ICE EVM_SC_0 (R147.2)
SPICLK: AMIC110 ICE EVM_Interfaces (R12.2 U15.6), AMIC110 ICE EVM_SC_0 (R145.2)
SPICS: AMIC110 ICE EVM_Interfaces (R13.2 U15.7), AMIC110 ICE EVM_SC_0 (R151.2)
SYS_BOOT6_GPIO: AMIC110 ICE EVM_BootConfig (R197.2), AMIC110 ICE EVM_SC_0 (U11.T3)
SYS_BOOT7_GPIO: AMIC110 ICE EVM_BootConfig (R198.2), AMIC110 ICE EVM_SC_0 (U11.T4)
SYS_RESETn: AMIC110 ICE EVM_Interfaces (5 pins), AMIC110 ICE EVM_SC_0 (R138.1 U11.A10)
UART0_RX: AMIC110 ICE EVM_Interfaces (R55.1 U12.C2), AMIC110 ICE EVM_SC_0 (U11.E15)
UART0_TX: AMIC110 ICE EVM_Interfaces (R76.2 U12.D2), AMIC110 ICE EVM_SC_0 (U11.E16)
UART1_DE: AMIC110 ICE EVM_Interfaces (U15.8), AMIC110 ICE EVM_SC_0 (U11.C13)
UART1_RX: AMIC110 ICE EVM_Interfaces (R215.1 U15.4), AMIC110 ICE EVM_SC_0 (U11.D16)
UART1_TX: AMIC110 ICE EVM_Interfaces (R216.2 U15.9), AMIC110 ICE EVM_SC_0 (U11.D15)

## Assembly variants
001: not fitted C44 C67 FID1 FID2 FID3 J2 R11 R12 R13 R49 R51 R54 R55 R65 R66 R71 R72 R74 R75 R76 R104 R105 R106 R107 R108 R109 R110 R111 R112 R113 R116 R117 R118 R120 R122 R133 R134 R173 R180 R181 R190 R211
